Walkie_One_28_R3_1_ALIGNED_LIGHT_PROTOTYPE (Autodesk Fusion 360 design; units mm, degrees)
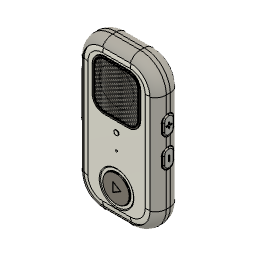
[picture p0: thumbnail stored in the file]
description: Open CASCADE Model
part number: Walkie_One_Concept_27_R2_REFERENCE_ASSEMBLY
description: Part Number
part number: C27_R2_04_Status_Lens
part number: C27_R2_05_Front_Switch_Clamp
part number: C27_R2_08_Volume_Down_Rigid_Carrier
part number: C27_R2_10_Front_Action_Pewter_Cap
part number: C27_R2_11_Front_Action_Bond_Film
part number: C27_R2_12_Volume_Up_Pewter_Cap
part number: C27_R2_13_Volume_Up_Bond_Film
part number: C27_R2_14_Volume_Down_Pewter_Cap
part number: C27_R2_15_Volume_Down_Bond_Film
base_feature "Base Feature1" bodies "C28_R3_1_01_Front_Shell_Aligned_Status_Light", "C28_R3_01_Front_Shell_Replaceable_Switch_Cassettes"
base_feature "Base Feature1" bodies "C28_R3_02_Back_Shell_Cassette_Keepers"
base_feature "Base Feature1" bodies "C28_R3_Front_Action_Carrier_Replaceable_Contact", "C28_R1_03_Round_Action_Carrier_Original_Retention"
base_feature "Base Feature1" bodies "C28_R3_1_04_Circular_Status_Lens_Coaxial_Flange", "C28_R1_04_Circular_Status_Lens_Original_Collector"
base_feature "Base Feature1" bodies "C28_R3_Front_Switch_Clamp_Adjustable_Seat_And_Stops"
base_feature "Base Feature1" bodies "C28_R3_PTT_Carrier_Replaceable_Contact"
base_feature "Base Feature1" bodies "C28_R3_Volume_Up_Carrier_Replaceable_Contact"
base_feature "Base Feature1" bodies "C28_R3_Volume_Down_Carrier_Replaceable_Contact"
base_feature "Base Feature1"
base_feature "Base Feature1" bodies "C28_R1_10_Round_Brushed_Steel_Play_Cap"
base_feature "Base Feature1" bodies "C28_R1_11_Round_Play_Bond_Film"
base_feature "Base Feature1"
base_feature "Base Feature1"
base_feature "Base Feature1"
base_feature "Base Feature1"
base_feature "Base Feature1" bodies "C28_R1_16_Smooth_Ember_PTT_Grip"
base_feature "Base Feature1"
base_feature "Base Feature1"
base_feature "Base Feature1"
base_feature "Base Feature1" bodies "C28_R2_PCB_Front_Seat_2_Y10p2_REVIEW", "C28_R2_PCB_Front_Seat_2_Y1p1_REVIEW"
base_feature "Base Feature1" bodies "C28_R2_PCB_Rear_Preload_2_Y10p2_REVIEW", "C28_R2_PCB_Rear_Preload_2_Y1p1_REVIEW"
base_feature "Base Feature1"
base_feature "Base Feature1"
base_feature "Base Feature1"
base_feature "Base Feature1"
base_feature "Base Feature1"
base_feature "Base Feature1"
base_feature "Base Feature1"
base_feature "Base Feature1"
base_feature "Base Feature1"
base_feature "Base Feature1"
base_feature "Base Feature1"
base_feature "Base Feature1"
base_feature "Base Feature1"
base_feature "Base Feature1"
base_feature "Base Feature1"
base_feature "Base Feature1"
base_feature "Base Feature1"
base_feature "Base Feature1"
base_feature "Base Feature1"
base_feature "Base Feature1"
base_feature "Base Feature1"
base_feature "Base Feature1" bodies "C28_R2_Microphone_Keeper_Passive_Reliefs_REVIEW"
base_feature "Base Feature1" bodies "C28_R2_Microphone_Rear_Preload_Passive_Reliefs_REVIEW"
base_feature "Base Feature1"
base_feature "Base Feature1"
base_feature "Base Feature1"
base_feature "Base Feature1"
base_feature "Base Feature1" bodies "C28_R2_Microphone_BOTTOM_PORT_Offset_Seal_REVIEW"
base_feature "Base Feature1"
base_feature "Base Feature1"
base_feature "Base Feature1"
base_feature "Base Feature1"
base_feature "Base Feature1"
base_feature "Base Feature1"
base_feature "Base Feature1"
base_feature "Base Feature1"
base_feature "Base Feature1"
base_feature "Base Feature1"
base_feature "Base Feature1"
base_feature "Base Feature1"
base_feature "Base Feature1"
base_feature "Base Feature1"
base_feature "Base Feature1"
base_feature "Base Feature1"
base_feature "Base Feature1"
base_feature "Base Feature1"
base_feature "Base Feature1"
base_feature "Base Feature1"
base_feature "Base Feature1"
base_feature "Base Feature1"
base_feature "Base Feature1"
base_feature "Base Feature1"
base_feature "Base Feature1"
base_feature "Base Feature1"
base_feature "Base Feature1"
base_feature "Base Feature1"
base_feature "Base Feature1"
base_feature "Base Feature1"
base_feature "Base Feature1"
base_feature "Base Feature1"
base_feature "Base Feature1"
base_feature "Base Feature1"
base_feature "Base Feature1"
base_feature "Base Feature1"
base_feature "Base Feature1"
base_feature "Base Feature1"
base_feature "Base Feature1"
base_feature "Base Feature1"
base_feature "Base Feature1"
base_feature "Base Feature1"
base_feature "Base Feature1"
base_feature "Base Feature1"
base_feature "Base Feature1"
base_feature "Base Feature1"
base_feature "Base Feature1"
base_feature "Base Feature1"
base_feature "Base Feature1"
base_feature "Base Feature1"
base_feature "Base Feature1"
base_feature "Base Feature1"
base_feature "Base Feature1"
base_feature "Base Feature1" bodies "C28_R1_57_Stainless_Grille_Bezel"
base_feature "Base Feature1" bodies "C28_R1_58_Grille_Perimeter_Bond_Film"
base_feature "Base Feature1" bodies "C28_R1_59_Mesh_Edge_Bond_Film"
base_feature "Base Feature1" bodies "C28_R1_60_Black_Acoustic_Scrim"
base_feature "Base Feature1" bodies "C28_R1_61_Graphite_Woven_Mesh_REFERENCE_RODS_001", "C28_R1_61_Graphite_Woven_Mesh_REFERENCE_RODS_002", "C28_R1_61_Graphite_Woven_Mesh_REFERENCE_RODS_003", "C28_R1_61_Graphite_Woven_Mesh_REFERENCE_RODS_004", "C28_R1_61_Graphite_Woven_Mesh_REFERENCE_RODS_005", "C28_R1_61_Graphite_Woven_Mesh_REFERENCE_RODS_006", "C28_R1_61_Graphite_Woven_Mesh_REFERENCE_RODS_007", "C28_R1_61_Graphite_Woven_Mesh_REFERENCE_RODS_008"
base_feature "Base Feature1" bodies "C28_R1_62_Scrim_Perimeter_Bond_Film"
sketch "C28_R1_CUT_Mesh_45x47_R10" plane through (0, 0, 0) normal (0, 0, 1) x axis (1, 0, 0)
  line L1 (12.5, -23.5) -> (-12.5, -23.5)
  line L2 (22.5, 13.5) -> (22.5, -13.5)
  line L3 (-12.5, 23.5) -> (12.5, 23.5)
  line L4 (-22.5, -13.5) -> (-22.5, 13.5)
  arc A1 centre (12.5, -13.5) radius 10 clockwise from (22.5, -13.5) to (12.5, -23.5)
  arc A2 centre (12.5, 13.5) radius 10 clockwise from (12.5, 23.5) to (22.5, 13.5)
  arc A3 centre (-12.5, 13.5) radius 10 clockwise from (-22.5, 13.5) to (-12.5, 23.5)
  arc A4 centre (-12.5, -13.5) radius 10 clockwise from (-12.5, -23.5) to (-22.5, -13.5)
sketch "C28_R1_CUT_Scrim_44_8x46_8_R9_9" plane through (0, 0, 0) normal (0, 0, 1) x axis (1, 0, 0)
  line L1 (12.5, -23.4) -> (-12.5, -23.4)
  line L2 (22.4, 13.5) -> (22.4, -13.5)
  line L3 (-12.5, 23.4) -> (12.5, 23.4)
  line L4 (-22.4, -13.5) -> (-22.4, 13.5)
  arc A1 centre (12.5, -13.5) radius 9.9 clockwise from (22.4, -13.5) to (12.5, -23.4)
  arc A2 centre (12.5, 13.5) radius 9.9 clockwise from (12.5, 23.4) to (22.4, 13.5)
  arc A3 centre (-12.5, 13.5) radius 9.9 clockwise from (-22.4, 13.5) to (-12.5, 23.4)
  arc A4 centre (-12.5, -13.5) radius 9.9 clockwise from (-12.5, -23.4) to (-22.4, -13.5)
sketch "C28_R1_CUT_Bezel_Plan_48x50" plane through (0, 0, 0) normal (0, 0, 1) x axis (1, 0, 0)
  line L1 (12.5, -25) -> (-12.5, -25)
  line L2 (24, 13.5) -> (24, -13.5)
  line L3 (-12.5, 25) -> (12.5, 25)
  line L4 (-24, -13.5) -> (-24, 13.5)
  line L5 (12.5, -23) -> (-12.5, -23)
  line L6 (22, 13.5) -> (22, -13.5)
  line L7 (-12.5, 23) -> (12.5, 23)
  line L8 (-22, -13.5) -> (-22, 13.5)
  arc A1 centre (12.5, -13.5) radius 11.5 clockwise from (24, -13.5) to (12.5, -25)
  arc A2 centre (12.5, 13.5) radius 11.5 clockwise from (12.5, 25) to (24, 13.5)
  arc A3 centre (-12.5, 13.5) radius 11.5 clockwise from (-24, 13.5) to (-12.5, 25)
  arc A4 centre (-12.5, -13.5) radius 11.5 clockwise from (-12.5, -25) to (-24, -13.5)
  arc A5 centre (12.5, -13.5) radius 9.5 clockwise from (22, -13.5) to (12.5, -23)
  arc A6 centre (12.5, 13.5) radius 9.5 clockwise from (12.5, 23) to (22, 13.5)
  arc A7 centre (-12.5, 13.5) radius 9.5 clockwise from (-22, 13.5) to (-12.5, 23)
  arc A8 centre (-12.5, -13.5) radius 9.5 clockwise from (-12.5, -23) to (-22, -13.5)
sketch "C28_R1_CUT_Grille_Perimeter_Bond" plane through (0, 0, 0) normal (0, 0, 1) x axis (1, 0, 0)
  line L1 (12.5, -24.9) -> (-12.5, -24.9)
  line L2 (23.9, 13.5) -> (23.9, -13.5)
  line L3 (-12.5, 24.9) -> (12.5, 24.9)
  line L4 (-23.9, -13.5) -> (-23.9, 13.5)
  line L5 (12.5, -23.8) -> (-12.5, -23.8)
  line L6 (22.8, 13.5) -> (22.8, -13.5)
  line L7 (-12.5, 23.8) -> (12.5, 23.8)
  line L8 (-22.8, -13.5) -> (-22.8, 13.5)
  arc A1 centre (12.5, -13.5) radius 11.4 clockwise from (23.9, -13.5) to (12.5, -24.9)
  arc A2 centre (12.5, 13.5) radius 11.4 clockwise from (12.5, 24.9) to (23.9, 13.5)
  arc A3 centre (-12.5, 13.5) radius 11.4 clockwise from (-23.9, 13.5) to (-12.5, 24.9)
  arc A4 centre (-12.5, -13.5) radius 11.4 clockwise from (-12.5, -24.9) to (-23.9, -13.5)
  arc A5 centre (12.5, -13.5) radius 10.3 clockwise from (22.8, -13.5) to (12.5, -23.8)
  arc A6 centre (12.5, 13.5) radius 10.3 clockwise from (12.5, 23.8) to (22.8, 13.5)
  arc A7 centre (-12.5, 13.5) radius 10.3 clockwise from (-22.8, 13.5) to (-12.5, 23.8)
  arc A8 centre (-12.5, -13.5) radius 10.3 clockwise from (-12.5, -23.8) to (-22.8, -13.5)
sketch "C28_R1_CUT_Mesh_Edge_Bond" plane through (0, 0, 0) normal (0, 0, 1) x axis (1, 0, 0)
  line L1 (12.5, -23.5) -> (-12.5, -23.5)
  line L2 (22.5, 13.5) -> (22.5, -13.5)
  line L3 (-12.5, 23.5) -> (12.5, 23.5)
  line L4 (-22.5, -13.5) -> (-22.5, 13.5)
  line L5 (12.5, -23) -> (-12.5, -23)
  line L6 (22, 13.5) -> (22, -13.5)
  line L7 (-12.5, 23) -> (12.5, 23)
  line L8 (-22, -13.5) -> (-22, 13.5)
  arc A1 centre (12.5, -13.5) radius 10 clockwise from (22.5, -13.5) to (12.5, -23.5)
  arc A2 centre (12.5, 13.5) radius 10 clockwise from (12.5, 23.5) to (22.5, 13.5)
  arc A3 centre (-12.5, 13.5) radius 10 clockwise from (-22.5, 13.5) to (-12.5, 23.5)
  arc A4 centre (-12.5, -13.5) radius 10 clockwise from (-12.5, -23.5) to (-22.5, -13.5)
  arc A5 centre (12.5, -13.5) radius 9.5 clockwise from (22, -13.5) to (12.5, -23)
  arc A6 centre (12.5, 13.5) radius 9.5 clockwise from (12.5, 23) to (22, 13.5)
  arc A7 centre (-12.5, 13.5) radius 9.5 clockwise from (-22, 13.5) to (-12.5, 23)
  arc A8 centre (-12.5, -13.5) radius 9.5 clockwise from (-12.5, -23) to (-22, -13.5)
sketch "C28_R1_CUT_Scrim_Perimeter_Bond" plane through (0, 0, 0) normal (0, 0, 1) x axis (1, 0, 0)
  line L1 (12.5, -23.3) -> (-12.5, -23.3)
  line L2 (22.3, 13.5) -> (22.3, -13.5)
  line L3 (-12.5, 23.3) -> (12.5, 23.3)
  line L4 (-22.3, -13.5) -> (-22.3, 13.5)
  line L5 (12.5, -22.4) -> (-12.5, -22.4)
  line L6 (21.4, 13.5) -> (21.4, -13.5)
  line L7 (-12.5, 22.4) -> (12.5, 22.4)
  line L8 (-21.4, -13.5) -> (-21.4, 13.5)
  arc A1 centre (12.5, -13.5) radius 9.8 clockwise from (22.3, -13.5) to (12.5, -23.3)
  arc A2 centre (12.5, 13.5) radius 9.8 clockwise from (12.5, 23.3) to (22.3, 13.5)
  arc A3 centre (-12.5, 13.5) radius 9.8 clockwise from (-22.3, 13.5) to (-12.5, 23.3)
  arc A4 centre (-12.5, -13.5) radius 9.8 clockwise from (-12.5, -23.3) to (-22.3, -13.5)
  arc A5 centre (12.5, -13.5) radius 8.9 clockwise from (21.4, -13.5) to (12.5, -22.4)
  arc A6 centre (12.5, 13.5) radius 8.9 clockwise from (12.5, 22.4) to (21.4, 13.5)
  arc A7 centre (-12.5, 13.5) radius 8.9 clockwise from (-21.4, 13.5) to (-12.5, 22.4)
  arc A8 centre (-12.5, -13.5) radius 8.9 clockwise from (-12.5, -22.4) to (-21.4, -13.5)
fillet "Fillet1" radius 0.6
work_plane "WorkPlane1" AlongDistance 0.51 ExtraOffset 0
sketch "Play symbol laser outline" plane through (0, 0, 0.51) normal (0, 0, 1) x axis (1, 0, 0)
  line L1 (5, -47) -> (-3.3, -52)
  line L2 (-3.3, -42) -> (5, -47)
  line L3 (-3.3, -52) -> (-3.3, -42)
  line L4 (4.42, -47) -> (-3, -51.469)
  line L5 (-3, -42.531) -> (4.42, -47)
  line L6 (-3, -51.469) -> (-3, -42.531)
extrude "Extrude1" cut sketch "Play symbol laser outline" along normal blind 0.1
base_feature "Base Feature1"
base_feature "Base Feature1"
base_feature "Base Feature1"
base_feature "Base Feature1"
base_feature "Base Feature1"
base_feature "Base Feature1"
base_feature "Base Feature1"
base_feature "Base Feature1"
base_feature "Base Feature1"
base_feature "Base Feature1"
base_feature "Base Feature1"
base_feature "Base Feature1"
base_feature "Base Feature1"
base_feature "Base Feature1"
base_feature "Base Feature1"
base_feature "Base Feature1"
base_feature "Base Feature1"
base_feature "Base Feature1"
base_feature "Base Feature1"
base_feature "Base Feature1"
base_feature "Base Feature1"
base_feature "Base Feature1"
base_feature "Base Feature1"
base_feature "Base Feature1"
base_feature "Base Feature1"
base_feature "Base Feature1"
base_feature "Base Feature1"
base_feature "Base Feature1" bodies "Nominal U6 envelope - NOT SUPPLIER MODEL"
base_feature "Base Feature1" bodies "Adafruit board XY from Eagle - 0p8 thickness UNVERIFIED", "SPH0645 nominal envelope - bottom acoustic port - internal MEMS omitted", "C2 nominal passive envelope HEIGHT UNVERIFIED", "C4 nominal passive envelope HEIGHT UNVERIFIED", "R1 nominal passive envelope HEIGHT UNVERIFIED", "R2 nominal passive envelope HEIGHT UNVERIFIED"
position "Position1"
base_feature "Base Feature1" bodies "C28_R3_PTT_Removable_Switch_Cradle"
base_feature "Base Feature1" bodies "C28_R3_PTT_Seat_Shim_0p40"
base_feature "Base Feature1" bodies "C28_R3_PTT_Cassette_Backing_0p15"
base_feature "Base Feature1" bodies "C28_R3_PTT_Rear_Keeper_Pad_0p50"
base_feature "Base Feature1" bodies "C28_R3_REF_PTT_LIDUOLE_NOMINAL_6mm_NOT_OEM_1", "C28_R3_REF_PTT_LIDUOLE_NOMINAL_6mm_NOT_OEM_2", "C28_R3_REF_PTT_LIDUOLE_NOMINAL_6mm_NOT_OEM_3", "C28_R3_REF_PTT_LIDUOLE_NOMINAL_6mm_NOT_OEM_4", "C28_R3_REF_PTT_LIDUOLE_NOMINAL_6mm_NOT_OEM_5", "C28_R3_REF_PTT_LIDUOLE_NOMINAL_6mm_NOT_OEM_6"
base_feature "Base Feature1" bodies "C28_R3_KEEP_OUT_PTT_Terminals_And_Solder_ESTIMATE_1", "C28_R3_KEEP_OUT_PTT_Terminals_And_Solder_ESTIMATE_2", "C28_R3_KEEP_OUT_PTT_Terminals_And_Solder_ESTIMATE_3", "C28_R3_KEEP_OUT_PTT_Terminals_And_Solder_ESTIMATE_4"
base_feature "Base Feature1" bodies "C28_R3_PTT_Compliant_Contact_25"
base_feature "Base Feature1" bodies "C28_R3_PTT_Travel_Stop_Shims_0p10_1", "C28_R3_PTT_Travel_Stop_Shims_0p10_2"
base_feature "Base Feature1" bodies "C28_R3_Volume_Up_Removable_Switch_Cradle"
base_feature "Base Feature1" bodies "C28_R3_Volume_Up_Seat_Shim_0p40"
base_feature "Base Feature1" bodies "C28_R3_Volume_Up_Cassette_Backing_0p15"
base_feature "Base Feature1" bodies "C28_R3_Volume_Up_Rear_Keeper_Pad_0p50"
base_feature "Base Feature1" bodies "C28_R3_REF_Volume_Up_LIDUOLE_NOMINAL_5mm_NOT_OEM_1", "C28_R3_REF_Volume_Up_LIDUOLE_NOMINAL_5mm_NOT_OEM_2", "C28_R3_REF_Volume_Up_LIDUOLE_NOMINAL_5mm_NOT_OEM_3", "C28_R3_REF_Volume_Up_LIDUOLE_NOMINAL_5mm_NOT_OEM_4", "C28_R3_REF_Volume_Up_LIDUOLE_NOMINAL_5mm_NOT_OEM_5", "C28_R3_REF_Volume_Up_LIDUOLE_NOMINAL_5mm_NOT_OEM_6"
base_feature "Base Feature1" bodies "C28_R3_KEEP_OUT_Volume_Up_Terminals_And_Solder_ESTIMATE_1", "C28_R3_KEEP_OUT_Volume_Up_Terminals_And_Solder_ESTIMATE_2", "C28_R3_KEEP_OUT_Volume_Up_Terminals_And_Solder_ESTIMATE_3", "C28_R3_KEEP_OUT_Volume_Up_Terminals_And_Solder_ESTIMATE_4"
base_feature "Base Feature1" bodies "C28_R3_Volume_Up_Compliant_Contact_20"
base_feature "Base Feature1" bodies "C28_R3_Volume_Up_Travel_Stop_Shims_0p10_1", "C28_R3_Volume_Up_Travel_Stop_Shims_0p10_2"
base_feature "Base Feature1" bodies "C28_R3_Volume_Down_Removable_Switch_Cradle"
base_feature "Base Feature1" bodies "C28_R3_Volume_Down_Seat_Shim_0p40"
base_feature "Base Feature1" bodies "C28_R3_Volume_Down_Cassette_Backing_0p15"
base_feature "Base Feature1" bodies "C28_R3_Volume_Down_Rear_Keeper_Pad_0p50"
base_feature "Base Feature1" bodies "C28_R3_REF_Volume_Down_LIDUOLE_NOMINAL_5mm_NOT_OEM_1", "C28_R3_REF_Volume_Down_LIDUOLE_NOMINAL_5mm_NOT_OEM_2", "C28_R3_REF_Volume_Down_LIDUOLE_NOMINAL_5mm_NOT_OEM_3", "C28_R3_REF_Volume_Down_LIDUOLE_NOMINAL_5mm_NOT_OEM_4", "C28_R3_REF_Volume_Down_LIDUOLE_NOMINAL_5mm_NOT_OEM_5", "C28_R3_REF_Volume_Down_LIDUOLE_NOMINAL_5mm_NOT_OEM_6"
base_feature "Base Feature1" bodies "C28_R3_KEEP_OUT_Volume_Down_Terminals_And_Solder_ESTIMATE_1", "C28_R3_KEEP_OUT_Volume_Down_Terminals_And_Solder_ESTIMATE_2", "C28_R3_KEEP_OUT_Volume_Down_Terminals_And_Solder_ESTIMATE_3", "C28_R3_KEEP_OUT_Volume_Down_Terminals_And_Solder_ESTIMATE_4"
base_feature "Base Feature1" bodies "C28_R3_Volume_Down_Compliant_Contact_20"
base_feature "Base Feature1" bodies "C28_R3_Volume_Down_Travel_Stop_Shims_0p10_1", "C28_R3_Volume_Down_Travel_Stop_Shims_0p10_2"
base_feature "Base Feature1" bodies "C28_R3_Front_Compliant_Contact_0p25"
base_feature "Base Feature1" bodies "C28_R3_Front_Seat_Shim_0p40"
base_feature "Base Feature1" bodies "C28_R3_Front_Travel_Stop_Shims_0p10_1", "C28_R3_Front_Travel_Stop_Shims_0p10_2"
base_feature "Base Feature1" bodies "C28_R3_REF_Front_LIDUOLE_NOMINAL_12x12x4p3_NOT_OEM_1", "C28_R3_REF_Front_LIDUOLE_NOMINAL_12x12x4p3_NOT_OEM_2", "C28_R3_REF_Front_LIDUOLE_NOMINAL_12x12x4p3_NOT_OEM_3", "C28_R3_REF_Front_LIDUOLE_NOMINAL_12x12x4p3_NOT_OEM_4", "C28_R3_REF_Front_LIDUOLE_NOMINAL_12x12x4p3_NOT_OEM_5", "C28_R3_REF_Front_LIDUOLE_NOMINAL_12x12x4p3_NOT_OEM_6"
base_feature "Base Feature1" bodies "C28_R3_KEEP_OUT_Front_Terminals_And_Solder_ESTIMATE_1", "C28_R3_KEEP_OUT_Front_Terminals_And_Solder_ESTIMATE_2", "C28_R3_KEEP_OUT_Front_Terminals_And_Solder_ESTIMATE_3", "C28_R3_KEEP_OUT_Front_Terminals_And_Solder_ESTIMATE_4"
sketch "R3 CUT Side_Seat_Shim_4p8x5p6" plane through (0, 0, 0) normal (0, 0, 1) x axis (1, 0, 0)
  line L1 (2.4, -2.8) -> (-2.4, -2.8)
  line L2 (2.4, 2.8) -> (2.4, -2.8)
  line L3 (-2.4, 2.8) -> (2.4, 2.8)
  line L4 (-2.4, -2.8) -> (-2.4, 2.8)
sketch "R3 CUT Side_Contact_2p4x2p2" plane through (0, 0, 0) normal (0, 0, 1) x axis (1, 0, 0)
  line L1 (1.2, -1.1) -> (-1.2, -1.1)
  line L2 (1.2, 1.1) -> (1.2, -1.1)
  line L3 (-1.2, 1.1) -> (1.2, 1.1)
  line L4 (-1.2, -1.1) -> (-1.2, 1.1)
sketch "R3 CUT PTT_Stop_1p6x2p1" plane through (0, 0, 0) normal (0, 0, 1) x axis (1, 0, 0)
  line L1 (0.8, -1.05) -> (-0.8, -1.05)
  line L2 (0.8, 1.05) -> (0.8, -1.05)
  line L3 (-0.8, 1.05) -> (0.8, 1.05)
  line L4 (-0.8, -1.05) -> (-0.8, 1.05)
sketch "R3 CUT Volume_Stop_1p6x1p7" plane through (0, 0, 0) normal (0, 0, 1) x axis (1, 0, 0)
  line L1 (0.8, -0.85) -> (-0.8, -0.85)
  line L2 (0.8, 0.85) -> (0.8, -0.85)
  line L3 (-0.8, 0.85) -> (0.8, 0.85)
  line L4 (-0.8, -0.85) -> (-0.8, 0.85)
sketch "R3 CUT Front_Stop_1p8x3p0" plane through (0, 0, 0) normal (0, 0, 1) x axis (1, 0, 0)
  line L1 (0.9, -1.5) -> (-0.9, -1.5)
  line L2 (0.9, 1.5) -> (0.9, -1.5)
  line L3 (-0.9, 1.5) -> (0.9, 1.5)
  line L4 (-0.9, -1.5) -> (-0.9, 1.5)
sketch "R3 CUT Front_Seat_Ring_10x10_Inner8x6" plane through (0, 0, 0) normal (0, 0, 1) x axis (1, 0, 0)
  line L1 (5, -5) -> (-5, -5)
  line L2 (5, 5) -> (5, -5)
  line L3 (-5, 5) -> (5, 5)
  line L4 (-5, -5) -> (-5, 5)
  line L5 (4, -3) -> (-4, -3)
  line L6 (4, 3) -> (4, -3)
  line L7 (-4, 3) -> (4, 3)
  line L8 (-4, -3) -> (-4, 3)
sketch "R3 CUT Front Contact d5" plane through (0, 0, 0) normal (0, 0, 1) x axis (1, 0, 0)
  circle C1 centre (0, 0) radius 2.5
position "Position2"
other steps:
create_component "CreateComponent1"
create_component "CreateComponent2"
create_component "CreateComponent3"
create_component "CreateComponent4"
create_component "CreateComponent5"
create_component "CreateComponent6"
create_component "CreateComponent7"
create_component "CreateComponent8"
create_component "CreateComponent9"
create_component "CreateComponent10"
create_component "CreateComponent11"
create_component "CreateComponent12"
create_component "CreateComponent13"
create_component "CreateComponent14"
create_component "CreateComponent15"
create_component "CreateComponent16"
create_component "CreateComponent17"
create_component "CreateComponent18"
create_component "CreateComponent19"
create_component "CreateComponent20"
create_component "CreateComponent21"
create_component "CreateComponent22"
create_component "CreateComponent23"
create_component "CreateComponent24"
create_component "CreateComponent25"
create_component "CreateComponent26"
create_component "CreateComponent27"
create_component "CreateComponent28"
create_component "CreateComponent29"
create_component "CreateComponent30"
create_component "CreateComponent31"
create_component "CreateComponent32"
create_component "CreateComponent33"
create_component "CreateComponent34"
create_component "CreateComponent35"
create_component "CreateComponent36"
create_component "CreateComponent37"
create_component "CreateComponent38"
create_component "CreateComponent39"
create_component "CreateComponent40"
create_component "CreateComponent41"
create_component "CreateComponent42"
create_component "CreateComponent43"
create_component "CreateComponent44"
create_component "CreateComponent45"
create_component "CreateComponent46"
create_component "CreateComponent47"
create_component "CreateComponent48"
create_component "CreateComponent49"
create_component "CreateComponent50"
create_component "CreateComponent51"
create_component "CreateComponent52"
create_component "CreateComponent53"
create_component "CreateComponent54"
create_component "CreateComponent55"
create_component "CreateComponent56"
create_component "CreateComponent57"
create_component "CreateComponent58"
create_component "CreateComponent59"
create_component "CreateComponent60"
create_component "CreateComponent61"
create_component "CreateComponent62"
create_component "CreateComponent63"
create_component "CreateComponent64"
create_component "CreateComponent65"
create_component "CreateComponent66"
create_component "CreateComponent67"
create_component "CreateComponent68"
create_component "CreateComponent69"
create_component "CreateComponent70"
create_component "CreateComponent71"
create_component "CreateComponent72"
create_component "CreateComponent73"
create_component "CreateComponent74"
create_component "CreateComponent75"
create_component "CreateComponent76"
create_component "CreateComponent77"
create_component "CreateComponent78"
create_component "CreateComponent79"
create_component "CreateComponent80"
create_component "CreateComponent81"
create_component "CreateComponent82"
create_component "CreateComponent83"
create_component "CreateComponent84"
create_component "CreateComponent85"
create_component "CreateComponent87"
create_component "CreateComponent1"
create_component "CreateComponent2"
create_component "CreateComponent88"
create_component "CreateComponent1"
create_component "CreateComponent2"
create_component "CreateComponent3"
create_component "CreateComponent4"
create_component "CreateComponent89"
create_component "CreateComponent1"
create_component "CreateComponent2"
create_component "CreateComponent95"
create_component "CreateComponent1"
create_component "CreateComponent2"
create_component "CreateComponent3"
create_component "CreateComponent4"
create_component "CreateComponent5"
create_component "CreateComponent6"
create_component "CreateComponent7"
create_component "CreateComponent96"
create_component "CreateComponent97"
create_component "CreateComponent98"
create_component "CreateComponent99"
create_component "CreateComponent100"
create_component "CreateComponent101"
create_component "CreateComponent102"
create_component "CreateComponent103"
create_component "CreateComponent104"
create_component "CreateComponent1"
create_component "CreateComponent1"
create_component "CreateComponent1"
create_component "CreateComponent2"
create_component "CreateComponent1"
create_component "CreateComponent3"
create_component "CreateComponent1"
create_component "CreateComponent4"
create_component "CreateComponent1"
create_component "CreateComponent5"
create_component "CreateComponent1"
create_component "CreateComponent6"
create_component "CreateComponent1"
create_component "CreateComponent7"
create_component "CreateComponent1"
create_component "CreateComponent8"
create_component "CreateComponent1"
create_component "CreateComponent9"
create_component "CreateComponent1"
create_component "CreateComponent10"
create_component "CreateComponent1"
create_component "CreateComponent11"
create_component "CreateComponent1"
create_component "CreateComponent1"
create_component "CreateComponent2"
create_component "CreateComponent12"
create_component "CreateComponent1"
create_component "CreateComponent13"
create_component "CreateComponent1"
create_component "CreateComponent14"
create_component "CreateComponent1"
create_component "CreateComponent1"
create_component "CreateComponent2"
create_component "CreateComponent15"
create_component "CreateComponent1"
create_component "CreateComponent16"
create_component "CreateComponent1"
create_component "CreateComponent1"
create_component "CreateComponent17"
create_component "CreateComponent1"
create_component "CreateComponent18"
create_component "CreateComponent1"
create_component "CreateComponent1"
create_component "CreateComponent2"
create_component "CreateComponent3"
create_component "CreateComponent4"
create_component "CreateComponent19"
create_component "CreateComponent1"
create_component "CreateComponent20"
create_component "CreateComponent1"
create_component "CreateComponent21"
create_component "CreateComponent1"
create_component "CreateComponent22"
create_component "CreateComponent105"
create_component "CreateComponent116"
create_component "CreateComponent123"
create_component "CreateComponent124"
create_component "CreateComponent125"
create_component "CreateComponent126"
create_component "CreateComponent127"
create_component "CreateComponent128"
create_component "CreateComponent129"
create_component "CreateComponent130"
create_component "CreateComponent131"
create_component "CreateComponent132"
create_component "CreateComponent133"
create_component "CreateComponent134"
create_component "CreateComponent135"
create_component "CreateComponent136"
create_component "CreateComponent137"
create_component "CreateComponent138"
create_component "CreateComponent139"
create_component "CreateComponent140"
create_component "CreateComponent141"
create_component "CreateComponent142"
create_component "CreateComponent143"
create_component "CreateComponent144"
create_component "CreateComponent145"
create_component "CreateComponent146"
create_component "CreateComponent147"
create_component "CreateComponent148"
create_component "CreateComponent149"
create_component "CreateComponent150"
create_component "CreateComponent151"
named bodies: "C28_R3_1_04_Circular_Status_Lens_Coaxial_Flange", "C28_R3_Front_Switch_Clamp_Adjustable_Seat_And_Stops", "C28_R3_Volume_Down_Carrier_Replaceable_Contact", "C28_R1_10_Round_Brushed_Steel_Play_Cap", "C28_R1_11_Round_Play_Bond_Film", "C28_R2_PCB_Front_Seat_2_Y10p2_REVIEW", "C28_R2_Microphone_BOTTOM_PORT_Offset_Seal_REVIEW", "C28_R3_Front_Action_Carrier_Replaceable_Contact", "C28_R3_PTT_Carrier_Replaceable_Contact", "C28_R2_PCB_Rear_Preload_2_Y10p2_REVIEW", "C28_R3_Volume_Up_Carrier_Replaceable_Contact", "C28_R2_Microphone_Keeper_Passive_Reliefs_REVIEW", "C28_R2_Microphone_Rear_Preload_Passive_Reliefs_REVIEW", "C28_R1_16_Smooth_Ember_PTT_Grip", "C28_R3_1_01_Front_Shell_Aligned_Status_Light", "C28_R3_02_Back_Shell_Cassette_Keepers", "C28_R3_01_Front_Shell_Replaceable_Switch_Cassettes", "C28_R1_03_Round_Action_Carrier_Original_Retention", "C28_R1_04_Circular_Status_Lens_Original_Collector", "C28_R2_PCB_Front_Seat_2_Y1p1_REVIEW", "C28_R2_PCB_Rear_Preload_2_Y1p1_REVIEW", "C28_R1_57_Stainless_Grille_Bezel", "C28_R1_58_Grille_Perimeter_Bond_Film", "C28_R1_59_Mesh_Edge_Bond_Film", "C28_R1_60_Black_Acoustic_Scrim", "C28_R1_61_Graphite_Woven_Mesh_REFERENCE_RODS_001", "C28_R1_61_Graphite_Woven_Mesh_REFERENCE_RODS_002", "C28_R1_61_Graphite_Woven_Mesh_REFERENCE_RODS_003", "C28_R1_61_Graphite_Woven_Mesh_REFERENCE_RODS_004", "C28_R1_61_Graphite_Woven_Mesh_REFERENCE_RODS_005", "C28_R1_61_Graphite_Woven_Mesh_REFERENCE_RODS_006", "C28_R1_61_Graphite_Woven_Mesh_REFERENCE_RODS_007", "C28_R1_61_Graphite_Woven_Mesh_REFERENCE_RODS_008", "C28_R1_61_Graphite_Woven_Mesh_REFERENCE_RODS_009", "C28_R1_61_Graphite_Woven_Mesh_REFERENCE_RODS_010", "C28_R1_61_Graphite_Woven_Mesh_REFERENCE_RODS_011", "C28_R1_61_Graphite_Woven_Mesh_REFERENCE_RODS_012", "C28_R1_61_Graphite_Woven_Mesh_REFERENCE_RODS_013", "C28_R1_61_Graphite_Woven_Mesh_REFERENCE_RODS_014", "C28_R1_61_Graphite_Woven_Mesh_REFERENCE_RODS_015", "C28_R1_61_Graphite_Woven_Mesh_REFERENCE_RODS_016", "C28_R1_61_Graphite_Woven_Mesh_REFERENCE_RODS_017", "C28_R1_61_Graphite_Woven_Mesh_REFERENCE_RODS_018", "C28_R1_61_Graphite_Woven_Mesh_REFERENCE_RODS_019", "C28_R1_61_Graphite_Woven_Mesh_REFERENCE_RODS_020", "C28_R1_61_Graphite_Woven_Mesh_REFERENCE_RODS_021", "C28_R1_61_Graphite_Woven_Mesh_REFERENCE_RODS_022", "C28_R1_61_Graphite_Woven_Mesh_REFERENCE_RODS_023", "C28_R1_61_Graphite_Woven_Mesh_REFERENCE_RODS_024", "C28_R1_61_Graphite_Woven_Mesh_REFERENCE_RODS_025", "C28_R1_61_Graphite_Woven_Mesh_REFERENCE_RODS_026", "C28_R1_61_Graphite_Woven_Mesh_REFERENCE_RODS_027", "C28_R1_61_Graphite_Woven_Mesh_REFERENCE_RODS_028", "C28_R1_61_Graphite_Woven_Mesh_REFERENCE_RODS_029", "C28_R1_61_Graphite_Woven_Mesh_REFERENCE_RODS_030", "C28_R1_61_Graphite_Woven_Mesh_REFERENCE_RODS_031", "C28_R1_61_Graphite_Woven_Mesh_REFERENCE_RODS_032", "C28_R1_61_Graphite_Woven_Mesh_REFERENCE_RODS_033", "C28_R1_61_Graphite_Woven_Mesh_REFERENCE_RODS_034", "C28_R1_61_Graphite_Woven_Mesh_REFERENCE_RODS_035"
